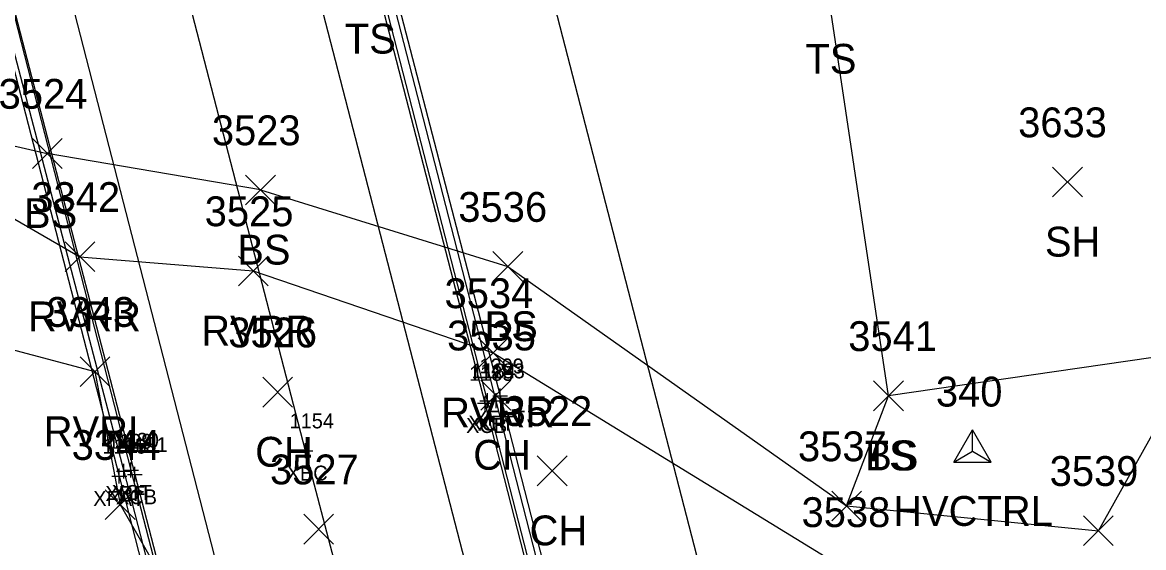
# Model space of a CAD drawing. Extents: x 1601151 to 1602912, y 499508 to 501770.
# Drawn here: x 1601542.5 to 1601617.7, y 500758.7 to 500794 of the extents above; entities that cross this region are included whole.
import ezdxf

# ---------------------------------------------------------------- set-up
doc = ezdxf.new("R2010")
doc.units = 0
for name, color, linetype in [('B_A', 7, 'Continuous'), ('B_I', 7, 'Continuous'), ('B_TIC', 7, 'Continuous'), ('BB', 7, 'Continuous'), ('BDC', 7, 'Continuous'), ('BELB', 7, 'Continuous'), ('BF', 7, 'Continuous'), ('BR', 7, 'Continuous'), ('C_A', 7, 'Continuous'), ('C_I', 7, 'Continuous'), ('CPSM', 7, 'Continuous'), ('L_A', 7, 'Continuous'), ('L_I', 7, 'Continuous'), ('L_TIC', 7, 'Continuous'), ('LAWE', 7, 'Continuous'), ('LELB', 7, 'Continuous'), ('UCO', 7, 'Continuous')]:
    doc.layers.add(name, color=color, linetype=linetype)

msp = doc.modelspace()

# ---------------------------------------------------------------- linework, layer by layer
at = {"layer": 'B_TIC'}
for p, q in [((1601573.702, 500768.593), (1601573.778, 500768.593)), ((1601574.292, 500768.594), (1601574.368, 500768.594)), ((1601574.555, 500768.924), (1601574.631, 500768.924)), ((1601573.538, 500768.43), (1601573.614, 500768.43)), ((1601561.501, 500765.241), (1601561.577, 500765.241)), ((1601549.018, 500763.542), (1601549.094, 500763.542)), ((1601549.329, 500763.869), (1601549.405, 500763.869)), ((1601549.803, 500763.941), (1601549.879, 500763.941)), ((1601550.062, 500763.65), (1601550.138, 500763.65))]:
    msp.add_line(p, q, dxfattribs=at)
for points in [[(1601574.552, 500768.424), (1601574.552, 500769.424)], [(1601573.199, 500768.593), (1601574.199, 500768.593)], [(1601573.535, 500767.93), (1601573.535, 500768.93)], [(1601573.699, 500768.093), (1601573.699, 500769.093)], [(1601573.789, 500768.594), (1601574.789, 500768.594)], [(1601574.052, 500768.924), (1601575.052, 500768.924)], [(1601574.289, 500768.094), (1601574.289, 500769.094)], [(1601573.035, 500768.43), (1601574.035, 500768.43)], [(1601561.498, 500764.741), (1601561.498, 500765.741)], [(1601560.998, 500765.241), (1601561.998, 500765.241)], [(1601549.015, 500763.042), (1601549.015, 500764.042)], [(1601549.326, 500763.369), (1601549.326, 500764.369)], [(1601549.8, 500763.441), (1601549.8, 500764.441)], [(1601550.059, 500763.15), (1601550.059, 500764.15)], [(1601548.515, 500763.542), (1601549.515, 500763.542)], [(1601548.826, 500763.869), (1601549.826, 500763.869)], [(1601549.3, 500763.941), (1601550.3, 500763.941)], [(1601549.559, 500763.65), (1601550.559, 500763.65)]]:
    msp.add_lwpolyline(points, dxfattribs=at)
at = {"layer": 'BB'}
for points in [[(1601612.43, 500602.27), (1601552.33, 500834.638)], [(1601596.605, 500598.195), (1601536.682, 500830.877)]]:
    msp.add_lwpolyline(points, dxfattribs=at)
at = {"layer": 'BDC'}
for points in [[(1601626.62, 500562.484), (1601618.762, 500592.927), (1601608.069, 500634.25), (1601598.914, 500669.817), (1601586.174, 500719.227), (1601573.535, 500768.43), (1601563.157, 500808.618), (1601554.18, 500843.361), (1601545.696, 500876.636)], [(1601627.365, 500562.647), (1601626.817, 500562.743), (1601626.575, 500563.06), (1601618.94, 500592.981), (1601608.354, 500634.47), (1601599.142, 500669.932), (1601586.408, 500719.217), (1601573.699, 500768.593), (1601563.408, 500808.684), (1601554.3, 500843.382), (1601545.843, 500876.671)], [(1601521.711, 500869.959), (1601522.401, 500870.191), (1601530.668, 500838.288), (1601539.742, 500803.087), (1601549.8, 500763.941), (1601562.902, 500713.198), (1601575.298, 500665.088), (1601584.682, 500628.799), (1601595.241, 500588.098), (1601603.293, 500556.622), (1601602.827, 500556.326)], [(1601522.54, 500870.251), (1601530.887, 500838.161), (1601539.773, 500803.176), (1601550.059, 500763.65), (1601563.09, 500713.388), (1601575.504, 500665.097), (1601584.832, 500628.831), (1601595.285, 500588.334), (1601603.432, 500556.591), (1601602.763, 500556.075)]]:
    msp.add_lwpolyline(points, dxfattribs=at)
at = {"layer": 'BELB'}
msp.add_lwpolyline([(1601614.122, 500560.679), (1601606.109, 500592.04), (1601595.825, 500632.34), (1601585.652, 500672.123), (1601574.355, 500716.245), (1601561.498, 500765.241), (1601551.327, 500804.521), (1601542.34, 500839.856), (1601533.48, 500873.114)], dxfattribs=at)
at = {"layer": 'BF'}
for points in [[(1601546.596, 500876.467), (1601555.117, 500843.825), (1601564.25, 500808.582), (1601574.552, 500768.924), (1601587.26, 500719.439), (1601599.8, 500670.488), (1601609.07, 500634.571), (1601619.784, 500593.212)], [(1601521.711, 500869.959), (1601529.926, 500837.537), (1601538.825, 500802.891), (1601549.015, 500763.542), (1601561.986, 500712.939), (1601574.422, 500664.924), (1601583.827, 500628.557), (1601594.342, 500587.938), (1601602.827, 500556.326)]]:
    msp.add_lwpolyline(points, dxfattribs=at)
at = {"layer": 'BR'}
for points in [[(1601626.891, 500563.91), (1601619.486, 500592.933), (1601608.823, 500634.178), (1601599.631, 500670.204), (1601586.939, 500719.228), (1601574.289, 500768.594), (1601563.976, 500808.593), (1601554.991, 500843.345), (1601546.615, 500875.695)], [(1601521.915, 500869.371), (1601530.025, 500838.058), (1601539.084, 500802.864), (1601549.326, 500763.869), (1601562.422, 500713.041), (1601574.564, 500665.146), (1601584.098, 500628.637), (1601594.598, 500587.839), (1601602.424, 500557.542)]]:
    msp.add_lwpolyline(points, dxfattribs=at)
at = {"layer": 'CPSM'}
for p, q in [((1601604.96, 500764.482), (1601606.21, 500766.647)), ((1601607.46, 500764.482), (1601606.21, 500766.647)), ((1601606.21, 500765.203), (1601606.21, 500766.647)), ((1601604.96, 500764.482), (1601606.21, 500765.203)), ((1601606.21, 500765.203), (1601606.21, 500765.203)), ((1601606.21, 500765.203), (1601607.46, 500764.482)), ((1601604.96, 500764.482), (1601607.46, 500764.482))]:
    msp.add_line(p, q, dxfattribs=at)
at = {"layer": 'L_TIC'}
for points in [[(1601543.19, 500784.17), (1601545.19, 500786.17)], [(1601545.19, 500784.17), (1601543.19, 500786.17)], [(1601543.19, 500784.17), (1601545.19, 500786.17)], [(1601545.19, 500784.17), (1601543.19, 500786.17)], [(1601557.485, 500781.723), (1601559.485, 500783.723)], [(1601559.485, 500781.723), (1601557.485, 500783.723)], [(1601557.485, 500781.723), (1601559.485, 500783.723)], [(1601559.485, 500781.723), (1601557.485, 500783.723)], [(1601611.583, 500782.258), (1601613.583, 500784.258)], [(1601613.583, 500782.258), (1601611.583, 500784.258)], [(1601545.382, 500777.247), (1601547.382, 500779.247)], [(1601547.382, 500777.247), (1601545.382, 500779.247)], [(1601557.004, 500776.295), (1601559.004, 500778.295)], [(1601559.004, 500776.295), (1601557.004, 500778.295)], [(1601574.063, 500776.588), (1601576.063, 500778.588)], [(1601576.063, 500776.588), (1601574.063, 500778.588)], [(1601573.084, 500770.8), (1601575.084, 500772.8)], [(1601575.084, 500770.8), (1601573.084, 500772.8)], [(1601546.387, 500769.546), (1601548.387, 500771.546)], [(1601548.387, 500769.546), (1601546.387, 500771.546)], [(1601558.639, 500768.17), (1601560.639, 500770.17)], [(1601560.639, 500768.17), (1601558.639, 500770.17)], [(1601573.257, 500767.966), (1601575.257, 500769.966)], [(1601575.257, 500767.966), (1601573.257, 500769.966)], [(1601599.579, 500767.923), (1601601.579, 500769.923)], [(1601601.579, 500767.923), (1601599.579, 500769.923)], [(1601599.579, 500767.923), (1601601.579, 500769.923)], [(1601601.579, 500767.923), (1601599.579, 500769.923)], [(1601577.035, 500762.898), (1601579.035, 500764.898)], [(1601579.035, 500762.898), (1601577.035, 500764.898)], [(1601548.082, 500760.625), (1601550.082, 500762.625)], [(1601550.082, 500760.625), (1601548.082, 500762.625)], [(1601596.777, 500760.537), (1601598.777, 500762.537)], [(1601598.777, 500760.537), (1601596.777, 500762.537)], [(1601596.777, 500760.537), (1601598.777, 500762.537)], [(1601598.777, 500760.537), (1601596.777, 500762.537)], [(1601561.382, 500758.987), (1601563.382, 500760.987)], [(1601563.382, 500758.987), (1601561.382, 500760.987)], [(1601613.656, 500758.88), (1601615.656, 500760.88)], [(1601615.656, 500758.88), (1601613.656, 500760.88)]]:
    msp.add_lwpolyline(points, dxfattribs=at)
at = {"layer": 'LAWE'}
for points in [[(1601318.619, 500789.616), (1601362.929, 500806.225), (1601394.458, 500804.484), (1601434.188, 500795.172), (1601527.957, 500788.908), (1601546.382, 500778.247), (1601558.004, 500777.295), (1601574.084, 500771.8), (1601598.015, 500757.122), (1601667.949, 500738.137), (1601705.277, 500715.12), (1601735.848, 500687.879), (1601768.331, 500671.256), (1601783.768, 500659.222)], [(1601521.092, 500757.434), (1601488.534, 500786.189), (1601547.387, 500770.546), (1601549.082, 500761.625), (1601572.731, 500720.13), (1601584.114, 500723.141), (1601587.174, 500723.02)]]:
    msp.add_lwpolyline(points, dxfattribs=at)
at = {"layer": 'LELB'}
for points in [[(1601316.838, 500806.724), (1601362.809, 500808.473), (1601394.06, 500806.297), (1601436.221, 500803.549), (1601489.343, 500796.426), (1601527.957, 500788.908), (1601544.19, 500785.17)], [(1601597.777, 500761.537), (1601600.579, 500768.923), (1601596.607, 500795.518)], [(1601558.485, 500782.723), (1601544.19, 500785.17)], [(1601558.485, 500782.723), (1601575.063, 500777.588), (1601597.777, 500761.537), (1601614.656, 500759.88), (1601621.402, 500771.941), (1601644.475, 500755.468), (1601669.056, 500742.24), (1601693.911, 500725.515), (1601707.664, 500718.532), (1601722.2, 500709.863), (1601744.29, 500697.943), (1601771.8, 500682.559), (1601891.409, 500620.783)], [(1601621.402, 500771.941), (1601600.579, 500768.923)]]:
    msp.add_lwpolyline(points, dxfattribs=at)
at = {"layer": 'UCO'}
msp.add_lwpolyline([(1601636.552, 500569.306), (1601558.395, 500871.752)], dxfattribs=at)

# ---------------------------------------------------------------- texts
at = {"layer": 'B_A'}
for s, p in [('XFAT', (1601572.808, 500766.924)), ('XCB', (1601572.271, 500766.43)), ('XCT', (1601572.419, 500766.593)), ('XRF', (1601573.049, 500766.594)), ('XBC', (1601560.234, 500763.241)), ('XFAT', (1601547.271, 500761.542)), ('XRF', (1601548.086, 500761.869)), ('XCT', (1601548.52, 500761.941)), ('XCB', (1601548.795, 500761.65))]:
    msp.add_text(s, height=1, dxfattribs=at).set_placement(p)
at = {"layer": 'B_I'}
for s, p in [('1185', (1601572.472, 500769.93)), ('1184', (1601572.636, 500770.093)), ('1209', (1601573.162, 500770.424)), ('1183', (1601573.226, 500770.094)), ('1154', (1601560.435, 500766.741)), ('1129', (1601548.259, 500765.369)), ('1130', (1601548.694, 500765.441)), ('1160', (1601547.885, 500765.042)), ('1131', (1601549.28, 500765.15))]:
    msp.add_text(s, height=1, dxfattribs=at).set_placement(p)
at = {"layer": 'C_A'}
msp.add_text('HVCTRL', height=2, dxfattribs=at).set_placement((1601600.903, 500760.203))
at = {"layer": 'C_I'}
msp.add_text('340', height=2, dxfattribs=at).set_placement((1601603.761, 500768.203))
at = {"layer": 'L_A'}
for s, p in [('TS', (1601564.137, 500791.869)), ('TS', (1601595.017, 500790.518)), ('TS', (1601595.017, 500790.518)), ('BS', (1601542.631, 500780.17)), ('BS', (1601542.631, 500780.17)), ('SH', (1601611.071, 500778.258)), ('BS', (1601556.926, 500777.723)), ('BS', (1601556.926, 500777.723)), ('RVRR', (1601542.894, 500773.247)), ('BS', (1601573.504, 500772.588)), ('RVRR', (1601554.516, 500772.295)), ('RVRR', (1601570.596, 500766.8)), ('RVRL', (1601543.954, 500765.546)), ('CH', (1601558.128, 500764.17)), ('CH', (1601572.746, 500763.966)), ('TS', (1601598.988, 500763.923)), ('BS', (1601599.02, 500763.923)), ('CH', (1601576.523, 500758.898))]:
    msp.add_text(s, height=2, dxfattribs=at).set_placement(p)
at = {"layer": 'L_I'}
for s, p in [('3524', (1601540.93, 500788.17)), ('3524', (1601540.93, 500788.17)), ('3633', (1601609.276, 500786.258)), ('3523', (1601555.225, 500785.723)), ('3523', (1601555.225, 500785.723)), ('3342', (1601543.122, 500781.247)), ('3525', (1601554.744, 500780.295)), ('3536', (1601571.748, 500780.588)), ('3534', (1601570.824, 500774.8)), ('3343', (1601544.127, 500773.546)), ('3526', (1601556.325, 500772.17)), ('3535', (1601570.998, 500771.966)), ('3541', (1601597.886, 500771.923)), ('3541', (1601597.886, 500771.923)), ('3522', (1601574.775, 500766.898)), ('3344', (1601545.822, 500764.625)), ('3537', (1601594.517, 500764.537)), ('3537', (1601594.517, 500764.537)), ('3527', (1601559.123, 500762.987)), ('3539', (1601611.388, 500762.88)), ('3538', (1601594.755, 500760.122))]:
    msp.add_text(s, height=2, dxfattribs=at).set_placement(p)

doc.saveas('drawing.dxf')
